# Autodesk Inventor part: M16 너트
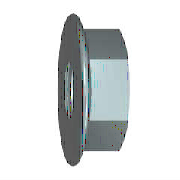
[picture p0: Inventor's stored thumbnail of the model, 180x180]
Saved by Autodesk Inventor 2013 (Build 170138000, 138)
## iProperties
IsCustomPart: 0
Created: 2009-02
Part Number: M16 너트
Material: 강철, 연강
Document SubType Name: Modeling
Standard: JIS B 1190
Designer: mdu
Standards Organization: JIS
Language: ko-KR
Size Designation: M 16
Categories: <MemberInstance><Categories><Category DisplayName="조임쇠" InternalName="e4da775c-781d-43d5-af7c-5136215cf5a6" Mnemonic="FSTN"><Category DisplayName="너트" InternalN
Density: 1 g/cm^3
Author: mdu
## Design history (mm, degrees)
sketch "스케치1"
  geometry: L1 (-3.414, 0)-(18.069, 0) reference; L2 (6.015, 11)-(3.359, 15.6); L3 (6.015, 11)-(15, 11); L4 (15, 11)-(15, 0); L5 (6.015, 11)-(6.015, 0); L6 (0, -3.378)-(0, 20.266) reference; A1 r 1.8 centre (1.8, 14.7) between (3.359, 15.6) and (0, 14.7); 1 further point
  constraints: 8 end point, 3 point on line, 2 perpendicular, 2 point on circle, 2 tangent, 1 centre point, 1 parallel
  dimensions: "d2" = 22 diameter of L3 L1 (= SW); "d4" = 33 dimension on A1 L1 (= LADI); "d5" = 1.8 radius of A1 (= PHH); "d15" = 15 distance between parallel lines of L4 L6 (= KOH); "d16" = 30 deg angle of L6 L2 (= KEWI)
revolve "링" sketch "스케치1" stored, may be unused: angle "d8" = 90 deg
sketch "스케치2"
  geometry: L1 (-11, -6.351)-(-11, 6.351); L2 (-11, 6.351)-(0, 12.702); L3 (0, 12.702)-(11, 6.351); L4 (11, 6.351)-(11, -6.351); L5 (11, -6.351)-(0, -12.702); L6 (0, -12.702)-(-11, -6.351); C1 r 4.9 at (0, 0); C2 r 14.7 at (0, 0) reference; 1 further point
  constraints: 12 end point, 1 centre point, 1 coincident, 1 vertical, 11 other
  dimensions: "d6" = 25.40341 distance of L5.end L2.end (= 1.1547 x SW)
extrude "본체" join sketch "스케치2" distance "d7" = 15 (= KOH); taper "d9" = 0 deg
sketch "스케치3"
  geometry: L1 (5.032, 12.702)-(15, 12.702) reference; L2 (15, 6.351)-(15, 12.702) reference; L3 (0, -14.7)-(0, 14.7) reference; L4 (-3, 0)-(18, 0) reference; L5 (14.018, 12.702)-(15, 11)
  constraints: 2 end point, 2 point on line
  dimensions: "d10" = 30 deg angle of L2 L5 (= ANG1); "d11" = 22 diameter of L5.end L4 (= SW0)
revolve "모따기1" sketch "스케치3" stored, may be unused: angle "d24" = 90 deg
sketch "스케치4"
  geometry: C1 r 14.7 at (0, 0) reference; 1 further point
  constraints: 1 coincident
hole "스레드" sketch "스케치4" at (0, 0) diameter "d25" = 13.835; stored, may be unused: countersink angle "d29" = 82 deg, drill point angle "d31" = 118 deg; dims "d26" = 6, "d27" = 4, "d28" = 2, "d30" = 8
workaxis "Work Axis1"
workplane "Work Plane1"
body "Solid1"
chamfer "모따기2" distance "d12" = 1.08253 (= -0.5 x GD1 + 0.5 x NND); stored, may be unused: angle "d13" = 30 deg, second distance "d46" = 1.08253 (= -0.5 x GD1 + 0.5 x NND)
chamfer "모따기3" distance "d51" = 1.08253 (= -0.5 x GD1 + 0.5 x NND); stored, may be unused: second distance "d52" = 2, angle "d53" = 45 deg
other parameters: "ANG1" = 30 deg [user parameter; used in 1 equation term], "KEWI" = 30 deg [user parameter; used in 1 equation term], "NND" = 16 [user parameter; used in 3 equation terms], "LADI" = 33 [user parameter; used in 2 equation terms], "SW" = 22 [user parameter; used in 4 equation terms], "PHH" = 1.8 [user parameter; used in 2 equation terms], "KOH" = 15 [user parameter; used in 2 equation terms], "SW0" = 22 (= SW) [user parameter; used in 1 equation term], "GD1" = 13.83494 (computed from THREADDIA, PTC, TOA) [user parameter; used in 3 equation terms], "d1" = 33 (= LADI), "d3" = 1.8 (= PHH), "d45" = 0, "d47" = 0, "d49" = 0, "d54" = 0, "GUL" = 1.08253 (= 0.541266 x PTC) [user parameter], "TPU" = 5 (computed from PTC) [user parameter], "RR" = 2 [user parameter], "THREADDIA" = 16 [user parameter; used in 1 equation term], "TOA" = 30 deg [user parameter; used in 1 equation term], "PTC" = 2 [user parameter; used in 4 equation terms], "GAL" = 1.08253 (= 0.541266 x PTC) [user parameter], "E0" = 25.41 (= 1.155 x SW) [user parameter]
